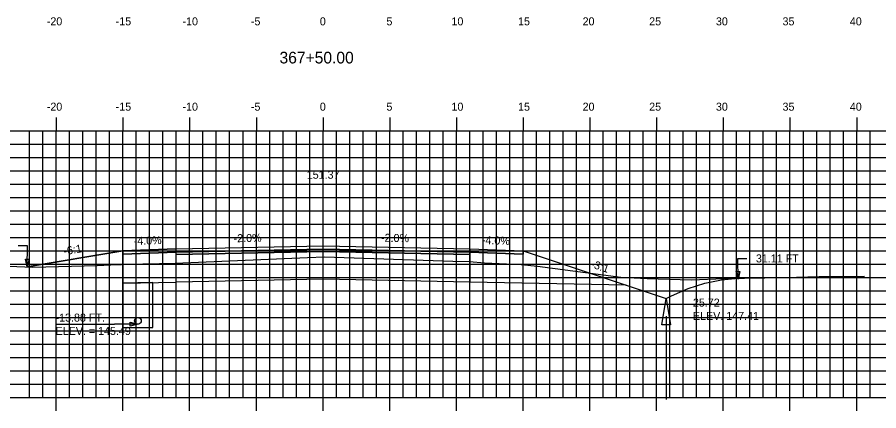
# Model space of a CAD drawing. Extents: x 1147633 to 1147803, y 608981 to 609091.
# Drawn here: x 1147693.5 to 1147758.1, y 609019.3 to 609048.8 of the extents above; entities that cross this region are included whole.
import ezdxf

# ---------------------------------------------------------------- set-up
doc = ezdxf.new("R2010")
doc.units = 0
for name, color, linetype in [('ANNOTATION', 7, 'Continuous'), ('D_Drainage_Ditch_Line', 7, 'Continuous'), ('D_Drainage_Underdrain', 7, 'Continuous'), ('D_Drainage_Underdrain_06in', 7, 'Continuous'), ('D_Roadway_Centerline', 7, 'Continuous'), ('D_Roadway_Centerline_Text', 7, 'Continuous'), ('D_Roadway_Edge_Shoulder', 7, 'Continuous'), ('D_Roadway_Edge_TW', 7, 'Continuous'), ('D_Roadway_Pavement', 7, 'Continuous'), ('D_Roadway_SlopeLines', 7, 'Continuous'), ('D_Roadway_SubGrade', 7, 'Continuous'), ('D_Text_Standard', 7, 'Continuous'), ('H_V ANNOTATION', 7, 'Continuous'), ('MAJOR', 7, 'Continuous'), ('MINOR', 7, 'Continuous'), ('S_Roadway_Centerline', 7, 'Continuous')]:
    doc.layers.add(name, color=color, linetype=linetype)

msp = doc.modelspace()

# ---------------------------------------------------------------- linework, layer by layer
msp.add_lwpolyline([(1147694.284, 609030.126), (1147701.453, 609031.32), (1147701.454, 609031.32), (1147705.454, 609031.48), (1147716.454, 609031.7), (1147727.454, 609031.48), (1147731.454, 609031.32), (1147739.177, 609028.746), (1147742.177, 609027.746), (1147742.569, 609027.942), (1147743.819, 609028.493), (1147745.069, 609028.898), (1147746.319, 609029.156), (1147747.569, 609029.267)])
at = {"layer": 'D_Drainage_Ditch_Line'}
msp.add_line((1147742.178, 609026.434), (1147742.177, 609020.19), dxfattribs=at)
msp.add_lwpolyline([(1147742.506, 609025.777), (1147741.849, 609025.777), (1147742.177, 609027.746)], close=True, dxfattribs=at)
at = {"layer": 'D_Drainage_Underdrain'}
msp.add_lwpolyline([(1147701.454, 609028.9), (1147701.454, 609025.57), (1147703.704, 609025.57), (1147703.704, 609028.945)], close=True, dxfattribs=at)
at = {"layer": 'D_Drainage_Underdrain_06in'}
msp.add_lwpolyline([(1147702.579, 609026.32), (1147702.656, 609026.308), (1147702.726, 609026.273), (1147702.781, 609026.217), (1147702.817, 609026.148), (1147702.829, 609026.07), (1147702.817, 609025.993), (1147702.781, 609025.923), (1147702.726, 609025.868), (1147702.656, 609025.833), (1147702.579, 609025.82), (1147702.502, 609025.833), (1147702.432, 609025.868), (1147702.377, 609025.923), (1147702.341, 609025.993), (1147702.329, 609026.07), (1147702.341, 609026.148), (1147702.377, 609026.217), (1147702.432, 609026.273), (1147702.502, 609026.308)], close=True, dxfattribs=at)
at = {"layer": 'D_Roadway_Edge_Shoulder'}
for points in [[(1147705.454, 609031.48), (1147701.454, 609031.32), (1147701.454, 609031.07), (1147705.454, 609031.23)], [(1147727.454, 609031.48), (1147731.454, 609031.32), (1147731.454, 609031.07), (1147727.454, 609031.23)]]:
    msp.add_lwpolyline(points, close=True, dxfattribs=at)
at = {"layer": 'D_Roadway_Edge_TW'}
msp.add_lwpolyline([(1147705.454, 609031.23), (1147705.454, 609031.48), (1147716.454, 609031.7), (1147727.454, 609031.48), (1147727.454, 609031.23), (1147716.454, 609031.45)], close=True, dxfattribs=at)
at = {"layer": 'D_Roadway_Pavement'}
msp.add_lwpolyline([(1147705.454, 609031.064), (1147705.454, 609031.23), (1147716.454, 609031.45), (1147727.454, 609031.23), (1147727.454, 609031.064), (1147716.454, 609031.284)], close=True, dxfattribs=at)
at = {"layer": 'D_Roadway_SlopeLines'}
for points in [[(1147701.454, 609031.32), (1147694.284, 609030.126)], [(1147742.177, 609027.746), (1147742.569, 609027.942), (1147743.819, 609028.493), (1147745.069, 609028.898), (1147746.319, 609029.156), (1147747.569, 609029.267)], [(1147739.177, 609028.746), (1147742.177, 609027.746)]]:
    msp.add_lwpolyline(points, dxfattribs=at)
at = {"layer": 'D_Roadway_SubGrade'}
for points in [[(1147705.454, 609031.064), (1147705.454, 609031.23), (1147701.454, 609031.07), (1147701.454, 609031.32), (1147701.453, 609031.32), (1147701.454, 609028.9), (1147705.454, 609028.98)], [(1147705.454, 609028.98), (1147705.454, 609031.064), (1147716.454, 609031.284), (1147727.454, 609031.064), (1147727.454, 609028.98), (1147716.454, 609029.2)], [(1147727.454, 609031.064), (1147727.454, 609031.23), (1147731.454, 609031.07), (1147731.454, 609031.32), (1147731.454, 609031.32), (1147739.177, 609028.746), (1147727.454, 609028.98)]]:
    msp.add_lwpolyline(points, close=True, dxfattribs=at)
at = {"layer": 'D_Text_Standard'}
msp.add_line((1147696.403, 609025.82), (1147700.817, 609025.82), dxfattribs=at)
for points in [[(1147694.284, 609030.126), (1147694.289, 609031.699), (1147693.609, 609031.699)], [(1147747.569, 609029.192), (1147747.539, 609030.757), (1147748.219, 609030.757)], [(1147702.579, 609025.82), (1147701.497, 609025.82), (1147700.817, 609025.82)]]:
    msp.add_lwpolyline(points, dxfattribs=at)
for points in [[(1147694.284, 609030.126), (1147694.141, 609030.708), (1147694.432, 609030.707)], [(1147747.569, 609029.192), (1147747.412, 609029.771), (1147747.703, 609029.776)], [(1147702.579, 609025.82), (1147701.997, 609025.675), (1147701.997, 609025.966)]]:
    msp.add_lwpolyline(points, close=True, dxfattribs=at)
at = {"layer": 'MAJOR'}
for p, q in [((1147696.454, 609041.337), (1147696.454, 609040.335)), ((1147701.454, 609041.337), (1147701.454, 609040.335)), ((1147706.454, 609041.337), (1147706.454, 609040.335)), ((1147711.454, 609041.337), (1147711.454, 609040.335)), ((1147716.454, 609041.337), (1147716.454, 609040.335)), ((1147721.454, 609041.337), (1147721.454, 609040.335)), ((1147726.454, 609041.337), (1147726.454, 609040.335)), ((1147731.454, 609041.337), (1147731.454, 609040.335)), ((1147736.454, 609041.337), (1147736.454, 609040.335)), ((1147741.454, 609041.337), (1147741.454, 609040.335)), ((1147746.454, 609041.337), (1147746.454, 609040.335)), ((1147751.454, 609041.337), (1147751.454, 609040.335)), ((1147756.454, 609041.337), (1147756.454, 609040.335)), ((1147646.454, 609040.335), (1147786.454, 609040.335)), ((1147646.454, 609040.335), (1147786.454, 609040.335)), ((1147696.454, 609020.335), (1147696.454, 609040.335)), ((1147701.454, 609020.335), (1147701.454, 609040.335)), ((1147706.454, 609020.335), (1147706.454, 609040.335)), ((1147711.454, 609020.335), (1147711.454, 609040.335)), ((1147716.454, 609020.335), (1147716.454, 609040.335)), ((1147721.454, 609020.335), (1147721.454, 609040.335)), ((1147726.454, 609020.335), (1147726.454, 609040.335)), ((1147731.454, 609020.335), (1147731.454, 609040.335)), ((1147736.454, 609020.335), (1147736.454, 609040.335)), ((1147741.454, 609020.335), (1147741.454, 609040.335)), ((1147746.454, 609020.335), (1147746.454, 609040.335)), ((1147751.454, 609020.335), (1147751.454, 609040.335)), ((1147756.454, 609020.335), (1147756.454, 609040.335)), ((1147646.454, 609035.335), (1147786.454, 609035.335)), ((1147646.454, 609030.335), (1147786.454, 609030.335)), ((1147646.454, 609025.335), (1147786.454, 609025.335)), ((1147646.454, 609020.335), (1147786.454, 609020.335)), ((1147646.454, 609020.335), (1147786.454, 609020.335)), ((1147696.454, 609019.333), (1147696.454, 609020.335)), ((1147701.454, 609019.333), (1147701.454, 609020.335)), ((1147706.454, 609019.333), (1147706.454, 609020.335)), ((1147711.454, 609019.333), (1147711.454, 609020.335)), ((1147716.454, 609019.333), (1147716.454, 609020.335)), ((1147721.454, 609019.333), (1147721.454, 609020.335)), ((1147726.454, 609019.333), (1147726.454, 609020.335)), ((1147731.454, 609019.333), (1147731.454, 609020.335)), ((1147736.454, 609019.333), (1147736.454, 609020.335)), ((1147741.454, 609019.333), (1147741.454, 609020.335)), ((1147746.454, 609019.333), (1147746.454, 609020.335)), ((1147751.454, 609019.333), (1147751.454, 609020.335)), ((1147756.454, 609019.333), (1147756.454, 609020.335))]:
    msp.add_line(p, q, dxfattribs=at)
at = {"layer": 'MINOR'}
for p, q in [((1147694.454, 609020.335), (1147694.454, 609040.335)), ((1147695.454, 609020.335), (1147695.454, 609040.335)), ((1147697.454, 609020.335), (1147697.454, 609040.335)), ((1147698.454, 609020.335), (1147698.454, 609040.335)), ((1147699.454, 609020.335), (1147699.454, 609040.335)), ((1147700.454, 609020.335), (1147700.454, 609040.335)), ((1147702.454, 609020.335), (1147702.454, 609040.335)), ((1147703.454, 609020.335), (1147703.454, 609040.335)), ((1147704.454, 609020.335), (1147704.454, 609040.335)), ((1147705.454, 609020.335), (1147705.454, 609040.335)), ((1147707.454, 609020.335), (1147707.454, 609040.335)), ((1147708.454, 609020.335), (1147708.454, 609040.335)), ((1147709.454, 609020.335), (1147709.454, 609040.335)), ((1147710.454, 609020.335), (1147710.454, 609040.335)), ((1147712.454, 609020.335), (1147712.454, 609040.335)), ((1147713.454, 609020.335), (1147713.454, 609040.335)), ((1147714.454, 609020.335), (1147714.454, 609040.335)), ((1147715.454, 609020.335), (1147715.454, 609040.335)), ((1147717.454, 609020.335), (1147717.454, 609040.335)), ((1147718.454, 609020.335), (1147718.454, 609040.335)), ((1147719.454, 609020.335), (1147719.454, 609040.335)), ((1147720.454, 609020.335), (1147720.454, 609040.335)), ((1147722.454, 609020.335), (1147722.454, 609040.335)), ((1147723.454, 609020.335), (1147723.454, 609040.335)), ((1147724.454, 609020.335), (1147724.454, 609040.335)), ((1147725.454, 609020.335), (1147725.454, 609040.335)), ((1147727.454, 609020.335), (1147727.454, 609040.335)), ((1147728.454, 609020.335), (1147728.454, 609040.335)), ((1147729.454, 609020.335), (1147729.454, 609040.335)), ((1147730.454, 609020.335), (1147730.454, 609040.335)), ((1147732.454, 609020.335), (1147732.454, 609040.335)), ((1147733.454, 609020.335), (1147733.454, 609040.335)), ((1147734.454, 609020.335), (1147734.454, 609040.335)), ((1147735.454, 609020.335), (1147735.454, 609040.335)), ((1147737.454, 609020.335), (1147737.454, 609040.335)), ((1147738.454, 609020.335), (1147738.454, 609040.335)), ((1147739.454, 609020.335), (1147739.454, 609040.335)), ((1147740.454, 609020.335), (1147740.454, 609040.335)), ((1147742.454, 609020.335), (1147742.454, 609040.335)), ((1147743.454, 609020.335), (1147743.454, 609040.335)), ((1147744.454, 609020.335), (1147744.454, 609040.335)), ((1147745.454, 609020.335), (1147745.454, 609040.335)), ((1147747.454, 609020.335), (1147747.454, 609040.335)), ((1147748.454, 609020.335), (1147748.454, 609040.335)), ((1147749.454, 609020.335), (1147749.454, 609040.335)), ((1147750.454, 609020.335), (1147750.454, 609040.335)), ((1147752.454, 609020.335), (1147752.454, 609040.335)), ((1147753.454, 609020.335), (1147753.454, 609040.335)), ((1147754.454, 609020.335), (1147754.454, 609040.335)), ((1147755.454, 609020.335), (1147755.454, 609040.335)), ((1147757.454, 609020.335), (1147757.454, 609040.335)), ((1147646.454, 609039.335), (1147786.454, 609039.335)), ((1147646.454, 609038.335), (1147786.454, 609038.335)), ((1147646.454, 609037.335), (1147786.454, 609037.335)), ((1147646.454, 609036.335), (1147786.454, 609036.335)), ((1147646.454, 609034.335), (1147786.454, 609034.335)), ((1147646.454, 609033.335), (1147786.454, 609033.335)), ((1147646.454, 609032.335), (1147786.454, 609032.335)), ((1147646.454, 609031.335), (1147786.454, 609031.335)), ((1147646.454, 609029.335), (1147786.454, 609029.335)), ((1147646.454, 609028.335), (1147786.454, 609028.335)), ((1147646.454, 609027.335), (1147786.454, 609027.335)), ((1147646.454, 609026.335), (1147786.454, 609026.335)), ((1147646.454, 609024.335), (1147786.454, 609024.335)), ((1147646.454, 609023.335), (1147786.454, 609023.335)), ((1147646.454, 609022.335), (1147786.454, 609022.335)), ((1147646.454, 609021.335), (1147786.454, 609021.335))]:
    msp.add_line(p, q, dxfattribs=at)
at = {"layer": 'S_Roadway_Centerline'}
msp.add_lwpolyline([(1147691.706, 609030.233), (1147694.696, 609030.108), (1147699.518, 609030.225), (1147700.55, 609030.28), (1147702.938, 609030.351), (1147704.193, 609030.38), (1147705.378, 609030.413), (1147715.28, 609030.839), (1147716.57, 609030.881), (1147726.193, 609030.554), (1147727.428, 609030.519), (1147728.551, 609030.439), (1147731.311, 609030.309), (1147732.534, 609030.167), (1147738.771, 609029.347), (1147740.754, 609029.25), (1147744.048, 609029.153), (1147746.526, 609029.247), (1147751.084, 609029.334), (1147753.652, 609029.403), (1147757.033, 609029.437)], dxfattribs=at)

# ---------------------------------------------------------------- texts
at = {"layer": 'ANNOTATION'}
for s, rotation, p in [('-4.0%', 2.29061, (1147702.27, 609031.754)), ('-2.0%', 1.14576, (1147709.757, 609031.967)), ('-2.0%', 358.85424, (1147720.797, 609032.014)), ('-4.0%', 357.70939, (1147728.35, 609031.845)), ('-6:1', 9.46352, (1147697.048, 609031)), ('-3:1', 341.56521, (1147736.465, 609030.104))]:
    msp.add_text(s, height=0.6, rotation=rotation, dxfattribs=at).set_placement(p)
at = {"layer": 'D_Roadway_Centerline'}
for s, p in [('C', (1147716.449, 609031.7)), ('L', (1147716.454, 609031.693))]:
    msp.add_text(s, height=0.0146, dxfattribs=at).set_placement(p)
at = {"layer": 'D_Roadway_Centerline_Text'}
msp.add_text('151.37', height=0.6, dxfattribs=at).set_placement((1147715.234, 609036.732))
at = {"layer": 'D_Text_Standard'}
for s, p in [('31.11 FT', (1147748.899, 609030.457)), ('25.72', (1147744.178, 609027.146)), ('-13.88 FT.', (1147696.403, 609026.02)), ('ELEV. 147.41', (1147744.178, 609026.144)), ('ELEV. = 145.49', (1147696.403, 609025.02))]:
    msp.add_text(s, height=0.6, dxfattribs=at).set_placement(p)
at = {"layer": 'H_V ANNOTATION'}
for s, height, p in [('-20', 0.6, (1147695.747, 609048.235)), ('-15', 0.6, (1147700.911, 609048.235)), ('-10', 0.6, (1147705.919, 609048.235)), ('-5', 0.6, (1147711.045, 609048.235)), ('0', 0.6, (1147716.213, 609048.235)), ('5', 0.6, (1147721.205, 609048.235)), ('10', 0.6, (1147726.079, 609048.235)), ('15', 0.6, (1147731.071, 609048.235)), ('20', 0.6, (1147735.908, 609048.235)), ('25', 0.6, (1147740.9, 609048.235)), ('30', 0.6, (1147745.903, 609048.235)), ('35', 0.6, (1147750.895, 609048.235)), ('40', 0.6, (1147755.94, 609048.235)), ('367+50.00', 0.875, (1147713.192, 609045.378)), ('-20', 0.6, (1147695.747, 609041.835)), ('-15', 0.6, (1147700.911, 609041.835)), ('-10', 0.6, (1147705.919, 609041.835)), ('-5', 0.6, (1147711.045, 609041.835)), ('0', 0.6, (1147716.213, 609041.835)), ('5', 0.6, (1147721.205, 609041.835)), ('10', 0.6, (1147726.079, 609041.835)), ('15', 0.6, (1147731.071, 609041.835)), ('20', 0.6, (1147735.908, 609041.835)), ('25', 0.6, (1147740.9, 609041.835)), ('30', 0.6, (1147745.903, 609041.835)), ('35', 0.6, (1147750.895, 609041.835)), ('40', 0.6, (1147755.94, 609041.835))]:
    msp.add_text(s, height=height, dxfattribs=at).set_placement(p)
at = {"layer": 'S_Roadway_Centerline'}
for s, p in [('C', (1147716.565, 609030.881)), ('L', (1147716.57, 609030.873))]:
    msp.add_text(s, height=0.0146, dxfattribs=at).set_placement(p)

doc.saveas('drawing.dxf')
